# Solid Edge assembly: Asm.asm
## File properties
Author: Deepak Maini
Template: Normal.asm
Last saved by: MYPC
Revision: 3
Application: Solid Edge
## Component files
multi-2-plate.par
handle ball.par
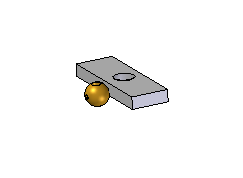
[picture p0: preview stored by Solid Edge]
